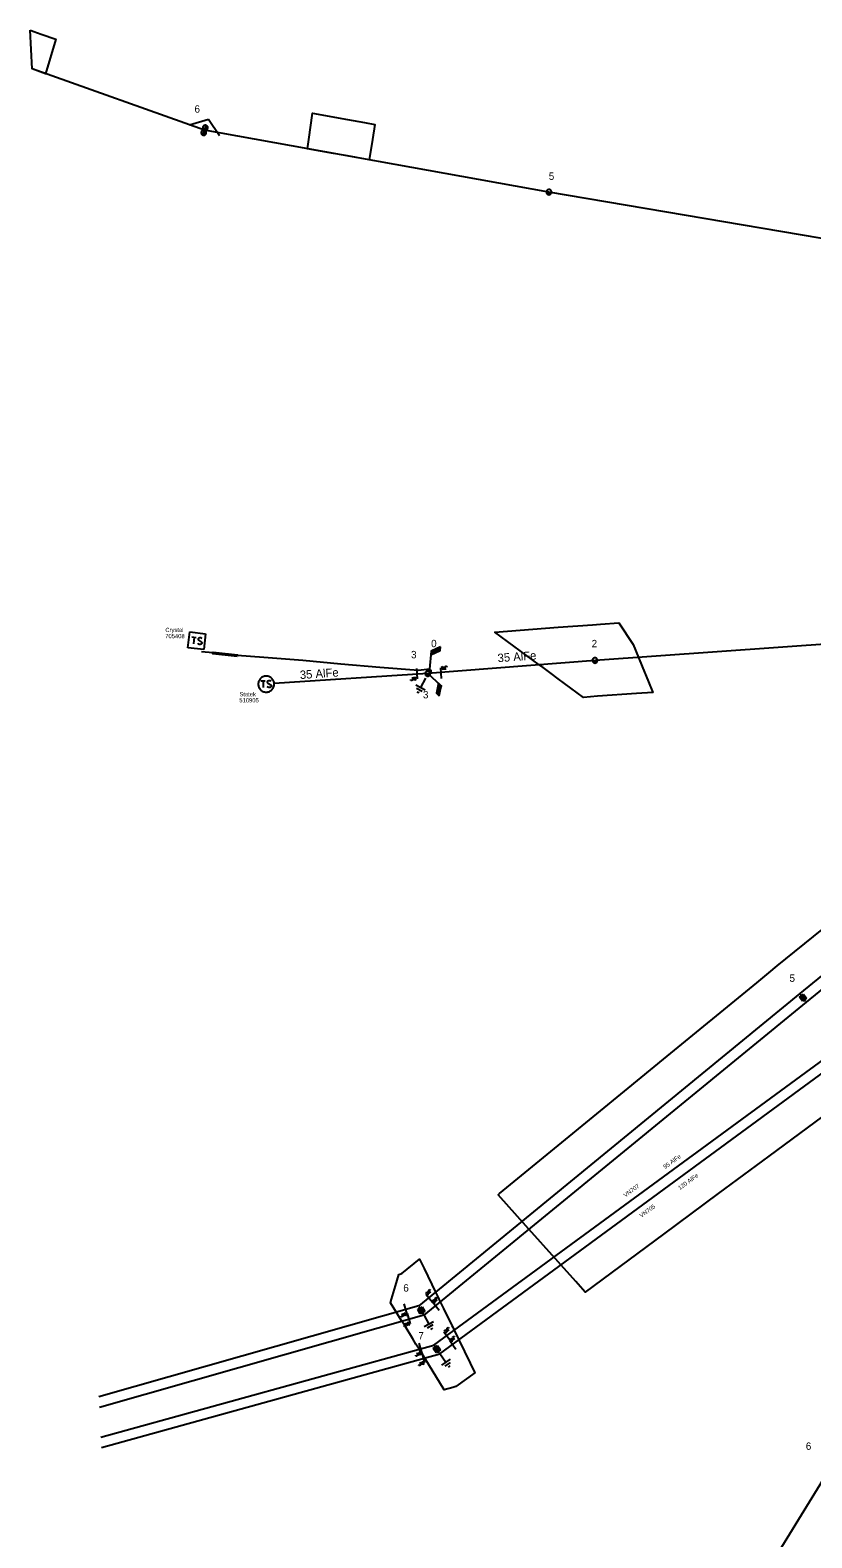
# Model space of a CAD drawing. Extents: x -545588 to -543214, y -1196037 to -1194452.
# Drawn here: x -545587.8 to -545402.3, y -1195194.1 to -1194836.6 of the extents above; entities that cross this region are included whole.
import ezdxf

# ---------------------------------------------------------------- set-up
doc = ezdxf.new("R2010")
doc.units = 0
for name, color, linetype in [('Default', 7, 'Continuous'), ('Vrstva 1', 7, 'Continuous'), ('Vrstva 11', 7, 'Continuous'), ('Vrstva 12', 7, 'Continuous'), ('Vrstva 13', 7, 'Continuous'), ('Vrstva 14', 7, 'Continuous'), ('Vrstva 15', 7, 'Continuous'), ('Vrstva 18', 7, 'Continuous'), ('Vrstva 2', 7, 'Continuous'), ('Vrstva 20', 7, 'Continuous'), ('Vrstva 25', 7, 'Continuous'), ('Vrstva 26', 7, 'Continuous'), ('Vrstva 27', 7, 'Continuous'), ('Vrstva 3', 7, 'Continuous'), ('Vrstva 35', 7, 'Continuous'), ('Vrstva 5', 7, 'Continuous'), ('Vrstva 52', 7, 'Continuous'), ('Vrstva 53', 7, 'Continuous'), ('Vrstva 6', 7, 'Continuous')]:
    doc.layers.add(name, color=color, linetype=linetype)

# ---------------------------------------------------------------- blocks, each defined once
blk = doc.blocks.new('VN840')
at = {"layer": 'Vrstva 15'}
for points in [[(-0.01, 1.41), (-0.01, -1.09)], [(-1.51, -1.24), (-1.51, -1.15)], [(-1.48, -1.35), (-1.51, -1.24)], [(-1.33, -1.42), (-1.48, -1.35)], [(-1.27, -1.42), (-1.33, -1.42)], [(-1.13, -1.35), (-1.27, -1.42)], [(-1.09, -1.24), (-1.13, -1.35)], [(-1.09, -0.59), (-1.09, -1.24)], [(-0.68, -0.59), (-0.68, -1.42)], [(-0.68, -1.11), (-0.27, -0.59)], [(-0.54, -0.94), (-0.2, -1.42)]]:
    blk.add_lwpolyline(points, dxfattribs=at)
blk = doc.blocks.new('VN860')
at = {"layer": 'Vrstva 15'}
for points in [[(-3.74, 0), (0.01, 2.82)], [(0.01, 2.82), (3.76, 0)]]:
    blk.add_lwpolyline(points, dxfattribs=at)
blk = doc.blocks.new('VN440')
at = {"layer": 'Vrstva 2'}
for points in [[(1.22, 0), (1.21, 0.13), (1.19, 0.25), (1.16, 0.38), (1.11, 0.5), (1.05, 0.61), (0.98, 0.72), (0.9, 0.82), (0.81, 0.91), (0.71, 0.99), (0.6, 1.06), (0.49, 1.12), (0.37, 1.16), (0.25, 1.2), (0.12, 1.22), (-0.01, 1.22), (-0.14, 1.22), (-0.26, 1.2), (-0.39, 1.16), (-0.51, 1.12), (-0.62, 1.06), (-0.73, 0.99), (-0.83, 0.91), (-0.92, 0.82), (-1, 0.72), (-1.07, 0.61), (-1.13, 0.5), (-1.18, 0.38), (-1.21, 0.25), (-1.23, 0.13), (-1.24, 0), (-1.23, -0.13), (-1.21, -0.26), (-1.18, -0.38), (-1.13, -0.5), (-1.07, -0.62), (-1, -0.73), (-0.92, -0.83), (-0.83, -0.92), (-0.73, -1), (-0.62, -1.07), (-0.51, -1.13), (-0.39, -1.17), (-0.26, -1.2), (-0.14, -1.23), (-0.01, -1.23), (0.12, -1.23), (0.25, -1.2), (0.37, -1.17), (0.49, -1.13), (0.6, -1.07), (0.71, -1), (0.81, -0.92), (0.9, -0.83), (0.98, -0.73), (1.05, -0.62), (1.11, -0.5), (1.16, -0.38), (1.19, -0.26), (1.21, -0.13), (1.22, 0)], [(-1.24, 0), (1.22, 0)], [(-1.18, -0.34), (1.1, -0.34)], [(-1.01, -0.63), (0.97, -0.63)], [(-0.74, -0.92), (0.68, -0.92)]]:
    blk.add_lwpolyline(points, dxfattribs=at)
blk = doc.blocks.new('VN810')
at = {"layer": 'Vrstva 14'}
for points in [[(0, -1.25), (0, -3.75)], [(1.25, -3.75), (-1.25, -3.75)], [(0.77, -4.37), (-0.8, -4.37)], [(0, -5), (-0.25, -5)], [(0.27, -5), (0, -5)]]:
    blk.add_lwpolyline(points, dxfattribs=at)
blk = doc.blocks.new('VN640')
at = {"layer": 'Vrstva 6'}
for points in [[(-1.89, 1.89), (1.89, 1.89)], [(-1.89, -1.89), (-1.89, 1.89)], [(-1.26, 0.79), (-0.22, 0.79)], [(-0.73, 0.79), (-0.73, -0.79)], [(1.2, 0.66), (0.94, 0.79), (0.66, 0.79), (0.41, 0.66), (0.28, 0.47), (0.28, 0.41), (0.41, 0.22), (1.13, -0.16), (1.26, -0.32), (1.26, -0.47), (1.13, -0.66), (0.91, -0.79), (0.63, -0.79), (0.5, -0.73), (0.28, -0.6)], [(1.89, 1.89), (1.89, -1.89)], [(1.89, -1.89), (-1.89, -1.89)]]:
    blk.add_lwpolyline(points, dxfattribs=at)
blk = doc.blocks.new('VN610')
at = {"layer": 'Vrstva 6'}
for points in [[(1.88, 0), (1.87, 0.2), (1.84, 0.39), (1.79, 0.58), (1.72, 0.77), (1.63, 0.94), (1.52, 1.11), (1.4, 1.26), (1.26, 1.4), (1.1, 1.53), (0.94, 1.63), (0.76, 1.72), (0.58, 1.8), (0.39, 1.85), (0.19, 1.88), (-0.01, 1.89), (-0.21, 1.88), (-0.4, 1.85), (-0.59, 1.8), (-0.78, 1.72), (-0.95, 1.63), (-1.12, 1.53), (-1.27, 1.4), (-1.41, 1.26), (-1.54, 1.11), (-1.64, 0.94), (-1.73, 0.77), (-1.8, 0.58), (-1.86, 0.39), (-1.89, 0.2), (-1.9, 0), (-1.89, -0.2), (-1.86, -0.39), (-1.8, -0.58), (-1.73, -0.77), (-1.64, -0.95), (-1.54, -1.11), (-1.41, -1.27), (-1.27, -1.41), (-1.12, -1.53), (-0.95, -1.64), (-0.78, -1.73), (-0.59, -1.8), (-0.4, -1.85), (-0.21, -1.88), (-0.01, -1.89), (0.19, -1.88), (0.39, -1.85), (0.58, -1.8), (0.76, -1.73), (0.94, -1.64), (1.1, -1.53), (1.26, -1.41), (1.4, -1.27), (1.52, -1.11), (1.63, -0.95), (1.72, -0.77), (1.79, -0.58), (1.84, -0.39), (1.87, -0.2), (1.88, 0)], [(-1.27, 0.78), (-0.26, 0.78)], [(-0.76, 0.78), (-0.76, -0.79)], [(1.19, 0.66), (0.94, 0.78), (0.62, 0.78), (0.37, 0.66), (0.24, 0.47), (0.24, 0.4), (0.37, 0.22), (1.12, -0.16), (1.25, -0.32), (1.25, -0.48), (1.12, -0.67), (0.87, -0.79), (0.62, -0.79), (0.49, -0.73), (0.24, -0.6)]]:
    blk.add_lwpolyline(points, dxfattribs=at)
blk = doc.blocks.new('VN450')
at = {"layer": 'Vrstva 2'}
for points in [[(0, 0), (-0.01, 0.13), (-0.03, 0.25), (-0.06, 0.38), (-0.11, 0.5), (-0.16, 0.61), (-0.23, 0.72), (-0.31, 0.82), (-0.4, 0.91), (-0.5, 0.99), (-0.61, 1.06), (-0.72, 1.11), (-0.84, 1.16), (-0.97, 1.19), (-1.09, 1.21), (-1.22, 1.22), (-1.35, 1.21), (-1.47, 1.19), (-1.59, 1.16), (-1.71, 1.11), (-1.83, 1.06), (-1.93, 0.99), (-2.03, 0.91), (-2.12, 0.82), (-2.2, 0.72), (-2.27, 0.61), (-2.33, 0.5), (-2.38, 0.38), (-2.41, 0.25), (-2.43, 0.13), (-2.44, 0), (-2.43, -0.13), (-2.41, -0.25), (-2.38, -0.38), (-2.33, -0.5), (-2.27, -0.61), (-2.2, -0.72), (-2.12, -0.82), (-2.03, -0.91), (-1.93, -0.99), (-1.83, -1.06), (-1.71, -1.11), (-1.59, -1.16), (-1.47, -1.19), (-1.35, -1.21), (-1.22, -1.22), (-1.09, -1.21), (-0.97, -1.19), (-0.84, -1.16), (-0.72, -1.11), (-0.61, -1.06), (-0.5, -0.99), (-0.4, -0.91), (-0.31, -0.82), (-0.23, -0.72), (-0.16, -0.61), (-0.11, -0.5), (-0.06, -0.38), (-0.03, -0.25), (-0.01, -0.13), (0, 0)], [(-2.44, 0), (2.44, 0)], [(2.44, 0), (2.43, 0.13), (2.41, 0.25), (2.38, 0.38), (2.33, 0.5), (2.27, 0.61), (2.2, 0.72), (2.12, 0.82), (2.03, 0.91), (1.94, 0.99), (1.83, 1.06), (1.71, 1.11), (1.6, 1.16), (1.47, 1.19), (1.35, 1.21), (1.22, 1.22), (1.09, 1.21), (0.97, 1.19), (0.84, 1.16), (0.72, 1.11), (0.61, 1.06), (0.5, 0.99), (0.4, 0.91), (0.31, 0.82), (0.23, 0.72), (0.16, 0.61), (0.11, 0.5), (0.06, 0.38), (0.03, 0.25), (0.01, 0.13), (0, 0), (0.01, -0.13), (0.03, -0.25), (0.06, -0.38), (0.11, -0.5), (0.16, -0.61), (0.23, -0.72), (0.31, -0.82), (0.4, -0.91), (0.5, -0.99), (0.61, -1.06), (0.72, -1.11), (0.84, -1.16), (0.97, -1.19), (1.09, -1.21), (1.22, -1.22), (1.35, -1.21), (1.47, -1.19), (1.6, -1.16), (1.71, -1.11), (1.83, -1.06), (1.94, -0.99), (2.03, -0.91), (2.12, -0.82), (2.2, -0.72), (2.27, -0.61), (2.33, -0.5), (2.38, -0.38), (2.41, -0.25), (2.43, -0.13), (2.44, 0)], [(-2.4, -0.31), (-0.04, -0.31)], [(-2.26, -0.61), (-0.17, -0.61)], [(-2.01, -0.92), (-0.42, -0.92)], [(0.04, -0.31), (2.4, -0.31)], [(0.17, -0.61), (2.27, -0.61)], [(0.42, -0.92), (2.02, -0.92)]]:
    blk.add_lwpolyline(points, dxfattribs=at)
blk = doc.blocks.new('VN001')
at = {"layer": 'Default'}
for p, q in [((2.05, 3.58), (4.46, 3.58)), ((2.07, 3.63), (4.49, 3.63)), ((2.1, 3.68), (4.52, 3.68)), ((2.13, 3.73), (2.54, 3.73)), ((1.73, 3.03), (4.14, 3.03)), ((1.76, 3.08), (4.17, 3.08)), ((1.79, 3.13), (4.2, 3.13)), ((1.82, 3.18), (4.23, 3.18)), ((1.85, 3.23), (4.26, 3.23)), ((1.87, 3.28), (4.29, 3.28)), ((1.9, 3.33), (4.32, 3.33)), ((1.93, 3.38), (4.35, 3.38)), ((1.96, 3.43), (4.37, 3.43)), ((1.99, 3.48), (4.4, 3.48)), ((2.02, 3.53), (4.43, 3.53))]:
    blk.add_line(p, q, dxfattribs=at)
blk.add_lwpolyline([(2.13, 3.73), (0, 0)], dxfattribs=at)
blk.add_lwpolyline([(4.55, 3.73), (2.13, 3.73), (1.7, 2.98), (4.12, 2.99)], close=True, dxfattribs=at)
blk = doc.blocks.new('VN470')
at = {"layer": 'Vrstva 2'}
for points in [[(-1.23, 1.22), (1.23, 1.22)], [(-1.23, -1.23), (-1.23, 1.22)], [(-0.92, 0.9), (0.92, 0.9)], [(-0.92, -0.95), (-0.92, 0.9)], [(-0.61, 0.61), (0.61, 0.61)], [(-0.61, -0.62), (-0.61, 0.61)], [(-0.31, -0.27), (-0.31, 0.34)], [(-0.31, 0.34), (0.31, 0.34)], [(0, 1.22), (0, 1.97)], [(0.31, 0.34), (0.31, -0.27)], [(0.61, 0.61), (0.61, -0.62)], [(0.92, 0.9), (0.92, -0.95)], [(1.23, 1.22), (1.23, -1.23)], [(1.23, -1.23), (-1.23, -1.23)], [(0.92, -0.95), (-0.92, -0.95)], [(0.61, -0.62), (-0.61, -0.62)], [(0.31, -0.27), (-0.31, -0.27)], [(0, -1.23), (0, -1.98)]]:
    blk.add_lwpolyline(points, dxfattribs=at)

msp = doc.modelspace()

# ---------------------------------------------------------------- linework, layer by layer
at = {"layer": 'Vrstva 1'}
for points in [[(-545292.23, -1194904.36), (-545301.79, -1194902.92), (-545381.67, -1194889.04), (-545464.66, -1194874.97), (-545546.4, -1194860.3), (-545587.31, -1194845.75)], [(-545290.64, -1194971.78), (-545405.11, -1195065.07), (-545495.54, -1195139.14), (-545571.44, -1195160.65)], [(-545289.27, -1194973.82), (-545403.67, -1195067.08), (-545494.32, -1195141.28), (-545571.32, -1195163.18)], [(-545231.73, -1194976.58), (-545288.13, -1195044.67), (-545343.3, -1195111.41), (-545397.6, -1195177.04), (-545441.95, -1195249.1), (-545485.78, -1195319.69), (-545525.23, -1195383.69), (-545557.58, -1195435.71)], [(-545570.96, -1195170.23), (-545491.96, -1195148.44), (-545395.75, -1195077.92)], [(-545570.84, -1195172.71), (-545490.55, -1195150.49), (-545394.22, -1195079.84)]]:
    msp.add_lwpolyline(points, dxfattribs=at)
at = {"layer": 'Vrstva 20'}
msp.add_lwpolyline([(-545538.64, -1194985.08), (-545544.42, -1194984.46), (-545544.38, -1194984.06), (-545538.6, -1194984.68)], close=True, dxfattribs=at)
at = {"layer": 'Vrstva 35'}
for points in [[(-545587.77, -1194836.56), (-545587.5, -1194836.66), (-545586.88, -1194836.88), (-545585.14, -1194837.5), (-545581.71, -1194838.72), (-545584.09, -1194846.89), (-545587.31, -1194845.75)], [(-545515.8, -1194865.8), (-545521.97, -1194864.69), (-545521.65, -1194862.5), (-545520.74, -1194856.27), (-545512.5, -1194857.75), (-545508.47, -1194858.47), (-545505.98, -1194858.92), (-545506.56, -1194862.5), (-545507.34, -1194867.31), (-545512.5, -1194866.39)], [(-545467, -1194987.05), (-545477.51, -1194979.3), (-545462.5, -1194978.19), (-545454.35, -1194977.59), (-545452.46, -1194977.46), (-545448.12, -1194977.15), (-545444.69, -1194982.29), (-545443.44, -1194985.34), (-545442.55, -1194987.5), (-545441.08, -1194991.08), (-545440.03, -1194993.62), (-545443.89, -1194993.89), (-545453.13, -1194994.55), (-545456.49, -1194994.8), (-545462.5, -1194990.37), (-545464.15, -1194989.15), (-545466.39, -1194987.5)], [(-545487.5, -1195158.46), (-545489.5, -1195159.02), (-545494.16, -1195151.49), (-545494.91, -1195150.28), (-545495.45, -1195149.41), (-545496.22, -1195148.17), (-545496.96, -1195146.96), (-545498.82, -1195143.96), (-545499.56, -1195142.77), (-545500.11, -1195141.87), (-545500.87, -1195140.65), (-545502.27, -1195138.39), (-545502.01, -1195137.5), (-545501.09, -1195134.37), (-545500.3, -1195131.65), (-545499.56, -1195131.44), (-545495.37, -1195128.02), (-545494.28, -1195130.26), (-545491.55, -1195135.87), (-545490.93, -1195137.15), (-545490.76, -1195137.5), (-545490.46, -1195138.12), (-545489.83, -1195139.42), (-545489.7, -1195139.7), (-545487.73, -1195143.73), (-545487.5, -1195144.2), (-545487.15, -1195144.92), (-545486.64, -1195145.98), (-545486.05, -1195147.19), (-545483.38, -1195152.69), (-545482.27, -1195154.96), (-545486.78, -1195158.26)]]:
    msp.add_lwpolyline(points, close=True, dxfattribs=at)
msp.add_lwpolyline([(-545390.67, -1195087.5), (-545412.5, -1195103.63), (-545424.51, -1195112.5), (-545437.5, -1195122.1), (-545456.09, -1195135.83), (-545458.33, -1195133.33), (-545462.5, -1195128.68), (-545470.14, -1195120.14), (-545476.74, -1195112.78), (-545476.4, -1195112.5), (-545462.5, -1195101.11), (-545445.89, -1195087.5), (-545437.5, -1195080.63), (-545415.37, -1195062.5), (-545412.5, -1195060.15), (-545410.48, -1195058.49), (-545399.88, -1195049.88)], dxfattribs=at)
at = {"layer": 'Vrstva 5'}
msp.add_lwpolyline([(-545493.42, -1194989.16), (-545493.04, -1194989.14), (-545492.62, -1194988.9), (-545492.61, -1194988.44), (-545493.02, -1194988.11), (-545495.65, -1194988.42), (-545504.82, -1194987.68), (-545514.07, -1194986.91), (-545523.03, -1194986.02), (-545532.32, -1194985.33), (-545538.62, -1194984.88), (-545544.4, -1194984.26), (-545547.11, -1194984)], dxfattribs=at)
at = {"layer": 'Vrstva 52'}
for points in [[(-545295.62, -1194964.82), (-545381.37, -1194980.94), (-545453.74, -1194986.07), (-545493.42, -1194989.16)], [(-545493.42, -1194989.16), (-545529.88, -1194991.52)]]:
    msp.add_lwpolyline(points, dxfattribs=at)

# ---------------------------------------------------------------- block references
at = {"layer": 'Vrstva 11'}
for p, rotation in [((-545493.02, -1194988.11), 24.089150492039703), ((-545493.42, -1194989.16), -102.34557422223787)]:
    msp.add_blockref('VN001', p, dxfattribs=dict(at, rotation=rotation))
at = {"layer": 'Vrstva 13'}
for name, p, xscale, yscale, rotation in [('VN450', (-545546.4, -1194860.3), 0.5000000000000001, 0.5, 72.48316394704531), ('VN440', (-545464.66, -1194874.97), 0.49999999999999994, 0.5000000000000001, -10.174947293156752), ('VN440', (-545453.74, -1194986.04), 0.5000000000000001, 0.5, 4.213244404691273), ('VN440', (-545493.42, -1194989.16), 0.5, 0.5, 4.498162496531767), ('VN470', (-545404.4, -1195066.03), 0.5, 0.5, 35.95226383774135), ('VN470', (-545494.98, -1195140.18), 0.5, 0.5, 28.75484165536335), ('VN470', (-545491.27, -1195149.4), 0.49999999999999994, 0.5000000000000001, 35.22301664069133)]:
    msp.add_blockref(name, p, dxfattribs=dict(at, xscale=xscale, yscale=yscale, rotation=rotation))
at = {"layer": 'Vrstva 15'}
for p, rotation in [((-545493.42, -1194989.16), -27.10344678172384), ((-545494.98, -1195140.18), 28.729269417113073), ((-545491.27, -1195149.4), 35.22301664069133)]:
    msp.add_blockref('VN810', p, dxfattribs=dict(at, rotation=rotation))
at = {"layer": 'Vrstva 18'}
for name, p, rotation in [('VN860', (-545546.4, -1194860.3), -19.579736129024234), ('VN840', (-545496.03, -1194989.33), 3.702913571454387), ('VN840', (-545490.28, -1194988.91), -175.50424709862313), ('VN840', (-545493.21, -1195137.23), -140.68283054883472), ('VN840', (-545498.67, -1195140.02), 15.82240275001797), ('VN840', (-545491.64, -1195139.09), -140.7008556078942), ('VN840', (-545497.88, -1195142.29), 15.874486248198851), ('VN840', (-545488.94, -1195146.23), -143.75576663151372), ('VN840', (-545487.58, -1195148.31), -143.74327498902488), ('VN840', (-545495.14, -1195149.32), 15.418513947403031), ('VN840', (-545494.45, -1195151.57), 15.474536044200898)]:
    msp.add_blockref(name, p, dxfattribs=dict(at, rotation=rotation))
at = {"layer": 'Vrstva 25'}
for name, p, rotation in [('VN640', (-545548.23, -1194981.38), -6.719183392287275), ('VN610', (-545531.75, -1194991.65), 0.014666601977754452)]:
    msp.add_blockref(name, p, dxfattribs=dict(at, rotation=rotation))

# ---------------------------------------------------------------- texts
at = {"layer": 'Vrstva 12'}
for s, p in [('0', (-545492.62, -1194982.9)), ('3', (-545494.57, -1194995.04))]:
    msp.add_text(s, height=1.75, dxfattribs=at).set_placement(p)
at = {"layer": 'Vrstva 14'}
for s, p in [('6', (-545548.77, -1194856.14)), ('5', (-545464.71, -1194872.07)), ('2', (-545454.54, -1194982.92)), ('3', (-545497.39, -1194985.53)), ('5', (-545407.59, -1195062.26)), ('6', (-545499.23, -1195135.73)), ('7', (-545495.66, -1195147.07)), ('6', (-545403.72, -1195173.25))]:
    msp.add_text(s, height=1.75, dxfattribs=at).set_placement(p)
at = {"layer": 'Vrstva 2'}
for s, rotation, p in [('95 AlFe', 36.244, (-545437.09, -1195106.68)), ('120 AlFe', 36.257, (-545433.58, -1195111.68))]:
    msp.add_text(s, height=1, rotation=rotation, dxfattribs=at).set_placement(p)
at = {"layer": 'Vrstva 26'}
msp.add_text('705408', height=1, dxfattribs=at).set_placement((-545555.72, -1194980.77))
msp.add_text('510905', height=1, rotation=0.015, dxfattribs=at).set_placement((-545538.13, -1194995.99))
at = {"layer": 'Vrstva 27'}
for s, p in [('Crystal', (-545555.69, -1194979.3)), ('Statek', (-545538.11, -1194994.55))]:
    msp.add_text(s, height=1, dxfattribs=at).set_placement(p)
at = {"layer": 'Vrstva 3'}
for s, rotation, p in [('VN707', 36.244, (-545446.51, -1195113.41)), ('VN705', 36.257, (-545442.72, -1195118.24))]:
    msp.add_text(s, height=1, rotation=rotation, dxfattribs=at).set_placement(p)
at = {"layer": 'Vrstva 53'}
for rotation, p in [(4.213, (-545476.78, -1194986.48)), (3.965, (-545523.71, -1194990.47))]:
    msp.add_text('35 AlFe', height=2, rotation=rotation, dxfattribs=at).set_placement(p)

doc.saveas('drawing.dxf')
